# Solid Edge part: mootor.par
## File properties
Author: Georg
Template: Iso Part.par
Last saved by: Kalle
Revision: 4
Application: Solid Edge
Accuracy: 0,990
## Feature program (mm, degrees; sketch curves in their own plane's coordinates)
sketch for "unnamed Protrusion 1" plane through (0, 0, 0) normal (0, 0, 1) x-axis (1, 0, 0)
  line (-10, -9) -> (10, -9)
  line (10, -9) -> (10, 9)
  line (10, 9) -> (-10, 9)
  line (-10, 9) -> (-10, -9)
  dimension (linear) = 10
  dimension (linear) = 10
extrude "unnamed Protrusion 1" add finite 12 along +normal
sketch for "unnamed Cutout 1" #1 plane through (10, 0, 6) normal (1, 0, 0) x-axis (0, 1, 0)
sketch for "unnamed Cutout 1" #2 plane through (10, 0, 6) normal (1, 0, 0) x-axis (0, 1, 0)
  line (1.5, 5) -> (6, 5)
  line (6, 5) -> (6, 6)
  line (6, 6) -> (1.5, 6)
  line (1.5, 6) -> (1.5, 5)
extrude "unnamed Cutout 1" cut to key point along -normal
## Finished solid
Body 1: solid body, 14 faces, 36 edges, 24 vertices.
  Faces by surface: plane 14
  Edges by curve: line 36
Bounding box of the edges (mm): 20.000 x 18.000 x 12.000, from (-10, -9, 0) to (10, 9, 12).
Planar faces by outward normal: +x 1, +y 3, +z 5, -x 1, -y 3, -z 1
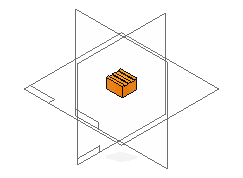
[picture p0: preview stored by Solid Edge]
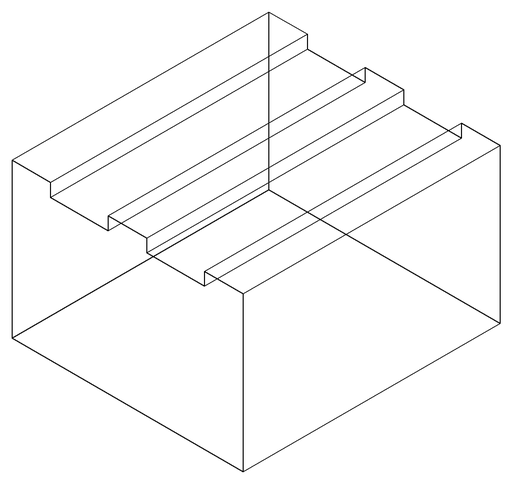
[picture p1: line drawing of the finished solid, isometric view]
